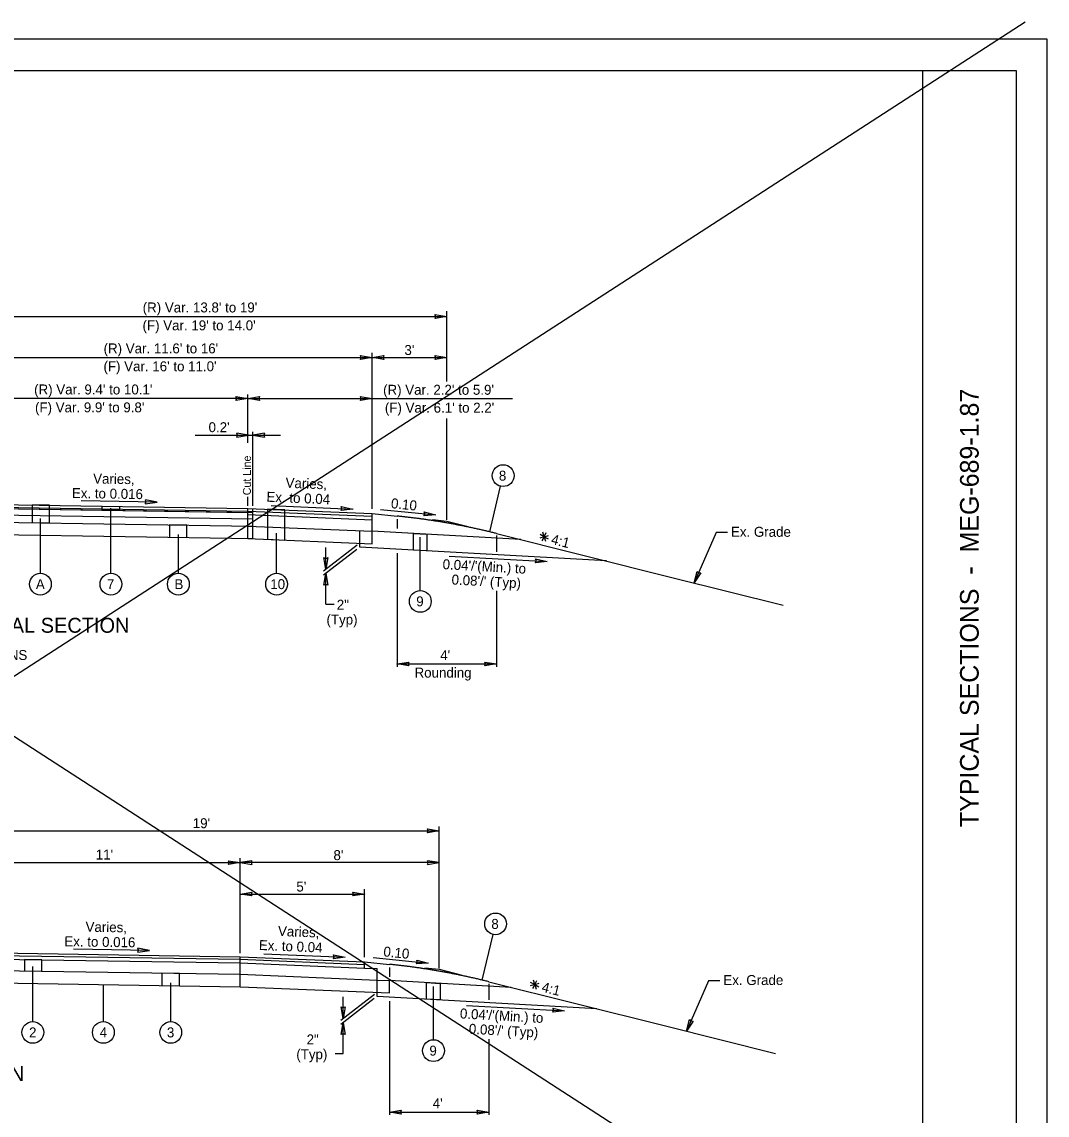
# Model space of a CAD drawing. Extents: x -268 to 840, y -210 to 226.
# Drawn here: x 400.5 to 482.9, y 24.1 to 112 of the extents above; entities that cross this region are included whole.
import ezdxf

# ---------------------------------------------------------------- set-up
doc = ezdxf.new("R2010")
doc.units = 0
for name, color, linetype in [('Level 1', 7, 'Continuous'), ('Level 16', 7, 'Continuous'), ('PV_X_Shoulder', 7, 'Continuous'), ('SH_Border', 7, 'Continuous'), ('SH_Data', 7, 'Continuous'), ('XS_P_Finished_Grade', 7, 'Continuous'), ('XS_X_Pavt', 7, 'Continuous')]:
    doc.layers.add(name, color=color, linetype=linetype)

msp = doc.modelspace()

# ---------------------------------------------------------------- linework, layer by layer
at = {"layer": 'Level 1'}
msp.add_lwpolyline([(312.91, 0.555), (482.91, 0.555), (482.91, 110.555), (312.91, 110.555)], close=True, dxfattribs=at)
at = {"layer": 'Level 16'}
msp.add_line((472.91, 3.055), (472.91, 108.055), dxfattribs=at)
msp.add_lwpolyline([(320.41, 108.055), (480.41, 108.055), (480.41, 3.055), (320.41, 3.055)], close=True, dxfattribs=at)
at = {"layer": 'PV_X_Shoulder'}
for p, q in [((311.141, 111.953), (481.141, 1.953)), ((311.141, 1.953), (481.141, 111.953))]:
    msp.add_line(p, q, dxfattribs=at)
at = {"layer": 'SH_Border'}
for points in [[(434.653, 88.284), (434.657, 88.282)], [(434.655, 88.284), (434.658, 88.282)], [(428.653, 84.984), (428.657, 84.982)], [(428.655, 84.984), (428.658, 84.982)], [(428.665, 84.981), (428.663, 84.983)], [(428.667, 84.981), (428.663, 84.983)], [(434.653, 84.984), (434.657, 84.982)], [(434.655, 84.984), (434.658, 84.982)], [(418.653, 81.684), (418.657, 81.682)], [(418.655, 81.684), (418.658, 81.682)], [(418.665, 81.681), (418.663, 81.683)], [(418.667, 81.681), (418.663, 81.683)], [(428.653, 81.684), (428.657, 81.682)], [(428.655, 81.684), (428.658, 81.682)], [(418.72, 78.726), (418.724, 78.728)], [(418.722, 78.726), (418.725, 78.728)], [(419.065, 78.729), (419.063, 78.727)], [(419.067, 78.729), (419.063, 78.727)], [(411.374, 73.348), (411.378, 73.35)], [(411.376, 73.348), (411.378, 73.35)], [(427.104, 72.804), (427.108, 72.802)], [(427.106, 72.805), (427.108, 72.802)], [(433.775, 72.33), (433.778, 72.328)], [(433.776, 72.331), (433.779, 72.328)], [(442.732, 68.576), (442.736, 68.574)], [(442.734, 68.577), (442.736, 68.574)], [(424.946, 67.956), (424.944, 67.952)], [(424.946, 67.954), (424.944, 67.952)], [(424.942, 67.623), (424.945, 67.625)], [(424.943, 67.621), (424.945, 67.625)], [(454.54, 66.868), (454.536, 66.866)], [(454.54, 66.87), (454.537, 66.867)], [(430.665, 60.346), (430.663, 60.349)], [(430.667, 60.347), (430.663, 60.349)], [(438.653, 60.349), (438.657, 60.347)], [(438.655, 60.35), (438.658, 60.347)], [(434.044, 46.938), (434.048, 46.936)], [(434.046, 46.938), (434.049, 46.936)], [(418.044, 44.383), (418.048, 44.381)], [(418.046, 44.383), (418.049, 44.381)], [(418.056, 44.383), (418.054, 44.381)], [(418.058, 44.383), (418.054, 44.381)], [(434.044, 44.38), (434.048, 44.382)], [(434.046, 44.38), (434.049, 44.382)], [(418.056, 41.858), (418.054, 41.861)], [(418.058, 41.859), (418.054, 41.861)], [(428.044, 41.861), (428.048, 41.859)], [(428.046, 41.862), (428.048, 41.859)], [(410.765, 37.324), (410.768, 37.326)], [(410.767, 37.324), (410.769, 37.326)], [(426.495, 36.78), (426.499, 36.778)], [(426.497, 36.781), (426.499, 36.778)], [(433.165, 36.306), (433.169, 36.304)], [(433.167, 36.306), (433.17, 36.304)], [(426.336, 31.849), (426.335, 31.845)], [(426.337, 31.847), (426.335, 31.844)], [(444.123, 32.469), (444.126, 32.467)], [(444.125, 32.469), (444.127, 32.467)], [(426.333, 31.516), (426.336, 31.518)], [(426.334, 31.514), (426.336, 31.517)], [(453.931, 30.846), (453.927, 30.843)], [(453.931, 30.844), (453.927, 30.842)], [(430.056, 24.322), (430.054, 24.325)], [(430.058, 24.323), (430.054, 24.325)], [(438.044, 24.325), (438.048, 24.323)], [(438.046, 24.326), (438.048, 24.323)]]:
    msp.add_lwpolyline(points, dxfattribs=at)
at = {"layer": 'SH_Data'}
for p, q in [((396.66, 88.283), (434.66, 88.283)), ((433.711, 88.441), (434.66, 88.283)), ((434.66, 88.283), (433.714, 88.124)), ((433.714, 88.124), (433.714, 88.124)), ((434.66, 83.061), (434.66, 88.711)), ((428.66, 72.816), (428.66, 85.363)), ((396.66, 84.983), (428.66, 84.983)), ((427.711, 85.141), (428.66, 84.983)), ((428.66, 84.983), (427.714, 84.824)), ((427.714, 84.824), (427.714, 84.824)), ((428.66, 84.983), (429.607, 85.141)), ((429.61, 84.824), (428.66, 84.983)), ((428.66, 84.983), (434.66, 84.983)), ((429.607, 85.141), (429.607, 85.141)), ((433.71, 85.141), (434.66, 84.983)), ((434.66, 84.983), (433.714, 84.824)), ((433.714, 84.824), (433.714, 84.824)), ((417.711, 81.841), (418.66, 81.683)), ((418.66, 78.118), (418.66, 82.001)), ((418.66, 81.683), (419.607, 81.841)), ((419.607, 81.841), (419.607, 81.841)), ((427.71, 81.841), (428.66, 81.683)), ((418.66, 81.683), (396.66, 81.683)), ((418.66, 81.683), (417.714, 81.524)), ((417.714, 81.524), (417.714, 81.524)), ((419.61, 81.524), (418.66, 81.683)), ((418.66, 81.683), (428.66, 81.683)), ((428.66, 81.683), (427.714, 81.524)), ((427.714, 81.524), (427.714, 81.524)), ((428.66, 81.683), (439.952, 81.683)), ((434.66, 71.93), (434.66, 80.067)), ((414.437, 78.728), (418.727, 78.728)), ((417.778, 78.569), (418.727, 78.728)), ((418.727, 78.728), (417.781, 78.886)), ((417.781, 78.886), (417.781, 78.886)), ((418.727, 78.728), (419.06, 78.728)), ((419.06, 73.047), (419.06, 79.014)), ((420.01, 78.886), (419.06, 78.728)), ((419.06, 78.728), (420.007, 78.569)), ((419.06, 78.728), (421.306, 78.728)), ((420.007, 78.569), (420.007, 78.569)), ((438.107, 70.968), (438.984, 74.632)), ((396.66, 73.198), (418.66, 72.849)), ((396.66, 72.989), (418.66, 72.641)), ((411.381, 73.349), (405.268, 73.447)), ((410.428, 73.214), (411.381, 73.349)), ((411.381, 73.349), (410.438, 73.53)), ((410.438, 73.53), (410.438, 73.53)), ((418.66, 73.058), (418.66, 73.78)), ((420.553, 73.076), (427.111, 72.803)), ((426.169, 73), (427.111, 72.803)), ((396.66, 72.864), (418.658, 72.516)), ((401.995, 67.638), (401.995, 72.051)), ((407.668, 67.638), (407.668, 72.873)), ((418.66, 72.849), (428.66, 72.433)), ((418.66, 72.516), (418.66, 72.849)), ((418.66, 72.641), (428.66, 72.224)), ((418.66, 70.433), (418.66, 72.516)), ((418.664, 72.349), (428.66, 71.933)), ((421.639, 70.308), (421.639, 72.725)), ((427.111, 72.803), (426.159, 72.684)), ((426.159, 72.684), (426.159, 72.684)), ((428.66, 71.933), (428.66, 72.433)), ((428.66, 72.433), (430.66, 72.233)), ((429.34, 72.772), (433.782, 72.328)), ((433.782, 72.328), (432.824, 72.265)), ((432.824, 72.265), (432.824, 72.265)), ((432.852, 72.58), (433.782, 72.328)), ((413.777, 70.509), (413.777, 71.51)), ((418.67, 71.432), (428.66, 71.016)), ((428.66, 71.016), (428.66, 71.933)), ((430.66, 71.976), (430.66, 71.226)), ((433.51, 71.948), (434.66, 71.833)), ((434.66, 71.833), (436.389, 71.4)), ((412.377, 70.532), (413.777, 70.509)), ((413.085, 67.638), (413.085, 70.747)), ((418.675, 70.432), (428.66, 70.016)), ((420.239, 70.367), (421.639, 70.308)), ((420.98, 67.638), (420.98, 70.851)), ((427.66, 70.058), (427.66, 71.058)), ((428.66, 70.016), (428.66, 71.016)), ((440.602, 70.347), (428.66, 71.016)), ((432.533, 66.255), (432.533, 70.532)), ((438.66, 70.833), (452.853, 67.284)), ((438.66, 70.664), (438.66, 69.37)), ((442.484, 70.572), (442.125, 70.463)), ((442.484, 70.572), (442.153, 70.749)), ((442.484, 70.572), (442.307, 70.241)), ((442.484, 70.572), (442.374, 70.931)), ((442.484, 70.572), (442.66, 70.903)), ((442.484, 70.572), (442.842, 70.682)), ((442.484, 70.572), (442.815, 70.396)), ((442.484, 70.572), (442.593, 70.214)), ((456.316, 70.906), (454.536, 66.864)), ((457.217, 70.906), (456.316, 70.906)), ((427.435, 69.561), (424.744, 67.473)), ((427.448, 69.893), (424.747, 67.796)), ((424.944, 67.949), (424.944, 69.697)), ((427.66, 69.737), (427.66, 70.07)), ((447.486, 68.626), (427.66, 69.737)), ((424.944, 67.949), (424.786, 68.896)), ((424.786, 68.896), (424.786, 68.896)), ((425.102, 68.899), (424.944, 67.949)), ((430.66, 69.262), (430.66, 60.13)), ((434.862, 69.016), (442.739, 68.575)), ((442.739, 68.575), (441.784, 68.481)), ((441.802, 68.797), (442.739, 68.575)), ((441.784, 68.481), (441.784, 68.481)), ((454.536, 66.864), (454.776, 67.793)), ((455.066, 67.668), (454.536, 66.864)), ((454.776, 67.793), (454.776, 67.793)), ((424.786, 66.678), (424.944, 67.628)), ((424.944, 65.155), (424.944, 67.628)), ((424.944, 67.628), (425.102, 66.681)), ((452.853, 67.284), (461.689, 65.076)), ((425.102, 66.681), (425.102, 66.681)), ((438.66, 66.226), (438.66, 60.13)), ((424.944, 65.155), (425.603, 65.155)), ((430.66, 60.348), (431.607, 60.506)), ((431.61, 60.19), (430.66, 60.348)), ((430.66, 60.348), (438.66, 60.348)), ((431.607, 60.506), (431.607, 60.506)), ((437.71, 60.506), (438.66, 60.348)), ((438.66, 60.348), (437.714, 60.19)), ((437.714, 60.19), (437.714, 60.19)), ((396.051, 46.936), (434.051, 46.936)), ((433.101, 47.094), (434.051, 46.936)), ((434.051, 46.936), (433.105, 46.778)), ((433.105, 46.778), (433.105, 46.778)), ((434.051, 35.906), (434.051, 47.277)), ((396.051, 44.382), (418.051, 44.382)), ((417.101, 44.54), (418.051, 44.382)), ((418.051, 44.382), (417.105, 44.223)), ((417.105, 44.223), (417.105, 44.223)), ((418.051, 37.106), (418.051, 44.749)), ((419.001, 44.54), (418.051, 44.382)), ((434.051, 44.382), (418.051, 44.382)), ((418.051, 44.382), (418.998, 44.223)), ((418.998, 44.223), (418.998, 44.223)), ((433.102, 44.223), (434.051, 44.382)), ((434.051, 44.382), (433.105, 44.54)), ((433.105, 44.54), (433.105, 44.54)), ((428.051, 36.792), (428.051, 42.253)), ((418.051, 41.86), (418.998, 42.018)), ((419.001, 41.702), (418.051, 41.86)), ((418.051, 41.86), (428.051, 41.86)), ((418.998, 42.018), (418.998, 42.018)), ((427.101, 42.018), (428.051, 41.86)), ((428.051, 41.86), (427.104, 41.702)), ((427.104, 41.702), (427.104, 41.702)), ((437.497, 34.944), (438.375, 38.608)), ((396.051, 37.173), (418.051, 36.825)), ((396.051, 36.965), (418.051, 36.617)), ((410.771, 37.325), (404.659, 37.423)), ((409.818, 37.19), (410.771, 37.325)), ((410.771, 37.325), (409.829, 37.506)), ((409.829, 37.506), (409.829, 37.506)), ((419.944, 37.052), (426.502, 36.778)), ((425.559, 36.976), (426.502, 36.778)), ((396.051, 36.673), (418.055, 36.325)), ((401.386, 31.613), (401.386, 36.027)), ((418.051, 36.825), (428.051, 36.409)), ((418.051, 34.408), (418.051, 36.825)), ((418.051, 34.377), (418.051, 36.793)), ((418.051, 36.617), (428.051, 36.2)), ((418.055, 36.325), (428.051, 35.909)), ((426.502, 36.778), (425.549, 36.66)), ((425.549, 36.66), (425.549, 36.66)), ((428.051, 35.909), (428.051, 36.409)), ((428.051, 36.409), (430.051, 36.209)), ((428.731, 36.748), (433.172, 36.304)), ((433.172, 36.304), (432.215, 36.241)), ((432.215, 36.241), (432.215, 36.241)), ((432.243, 36.556), (433.172, 36.304)), ((396.051, 35.757), (418.061, 35.408)), ((413.168, 34.485), (413.168, 35.486)), ((418.061, 35.408), (429.051, 34.95)), ((428.051, 35.909), (429.051, 35.867)), ((429.051, 34.95), (429.051, 35.867)), ((430.051, 35.952), (430.051, 35.202)), ((432.901, 35.924), (434.051, 35.809)), ((434.051, 35.809), (435.78, 35.376)), ((396.051, 34.756), (418.066, 34.408)), ((407.058, 31.613), (407.058, 34.582)), ((411.768, 34.508), (413.168, 34.485)), ((412.476, 31.613), (412.476, 34.723)), ((418.066, 34.408), (430.051, 33.909)), ((429.051, 34.95), (430.051, 34.909)), ((429.051, 33.95), (429.051, 34.95)), ((430.051, 33.909), (430.051, 34.909)), ((439.845, 34.36), (430.051, 34.909)), ((433.59, 30.148), (433.59, 34.424)), ((438.051, 34.809), (452.244, 31.26)), ((438.051, 34.639), (438.051, 33.346)), ((441.727, 34.585), (441.368, 34.476)), ((441.727, 34.585), (441.396, 34.762)), ((441.727, 34.585), (441.55, 34.254)), ((441.727, 34.585), (441.617, 34.944)), ((441.727, 34.585), (441.903, 34.916)), ((441.727, 34.585), (442.085, 34.694)), ((441.727, 34.585), (442.058, 34.409)), ((441.727, 34.585), (441.836, 34.227)), ((455.707, 34.882), (453.927, 30.84)), ((456.608, 34.882), (455.707, 34.882)), ((428.826, 33.454), (426.135, 31.365)), ((428.839, 33.785), (426.138, 31.689)), ((426.335, 31.842), (426.335, 33.59)), ((429.051, 33.629), (429.051, 33.963)), ((446.729, 32.639), (429.051, 33.629)), ((426.335, 31.842), (426.177, 32.788)), ((426.177, 32.788), (426.177, 32.788)), ((426.493, 32.791), (426.335, 31.842)), ((430.051, 33.238), (430.051, 24.106)), ((436.253, 32.908), (444.13, 32.467)), ((443.193, 32.69), (444.13, 32.467)), ((444.13, 32.467), (443.174, 32.374)), ((443.174, 32.374), (443.174, 32.374)), ((453.927, 30.84), (454.167, 31.769)), ((454.457, 31.643), (453.927, 30.84)), ((454.167, 31.769), (454.167, 31.769)), ((426.177, 30.571), (426.335, 31.521)), ((426.335, 29.048), (426.335, 31.521)), ((426.335, 31.521), (426.493, 30.574)), ((452.244, 31.26), (461.08, 29.052)), ((426.493, 30.574), (426.493, 30.574)), ((438.051, 30.202), (438.051, 24.106)), ((425.676, 29.048), (426.335, 29.048)), ((430.051, 24.324), (430.998, 24.482)), ((431.001, 24.166), (430.051, 24.324)), ((430.051, 24.324), (438.051, 24.324)), ((430.998, 24.482), (430.998, 24.482)), ((437.101, 24.482), (438.051, 24.324)), ((438.051, 24.324), (437.104, 24.166)), ((437.104, 24.166), (437.104, 24.166))]:
    msp.add_line(p, q, dxfattribs=at)
for points in [[(402.724, 71.685), (402.724, 73.102), (401.324, 73.124), (401.324, 71.707)], [(406.962, 73.034), (408.362, 73.012), (408.362, 72.679), (406.962, 72.701)], [(431.975, 70.83), (433.065, 70.769), (433.065, 69.434), (431.975, 69.495)], [(402.115, 35.661), (402.115, 36.577), (400.715, 36.599), (400.715, 35.683)], [(433.025, 34.742), (434.115, 34.681), (434.115, 33.346), (433.025, 33.407)]]:
    msp.add_lwpolyline(points, close=True, dxfattribs=at)
for points in [[(421.639, 72.725), (420.239, 72.783), (420.239, 70.367)], [(413.777, 71.51), (412.377, 71.532), (412.377, 70.532)], [(413.168, 35.486), (411.768, 35.508), (411.768, 34.508)]]:
    msp.add_lwpolyline(points, dxfattribs=at)
for centre in [(439.188, 75.483), (401.995, 66.763), (407.668, 66.763), (413.085, 66.763), (420.98, 66.763), (432.533, 65.38), (438.579, 39.459), (401.386, 30.738), (407.058, 30.738), (412.476, 30.738), (433.59, 29.273)]:
    msp.add_circle(centre, 0.875, dxfattribs=at)
for centre, start, end in [((433.472, 88.28), 327.14123, 33.822), ((427.472, 84.98), 327.14123, 33.822), ((429.849, 84.984), 147.14123, 213.822), ((433.472, 84.981), 327.14123, 33.822), ((417.472, 81.68), 327.14123, 33.822), ((419.849, 81.684), 147.14123, 213.822), ((427.472, 81.681), 327.14123, 33.822), ((417.539, 78.73), 326.178, 32.85877), ((420.249, 78.726), 146.178, 212.85877), ((410.192, 73.38), 324.80397, 31.48474), ((425.923, 72.85), 324.75531, 31.43608), ((432.598, 72.444), 321.43103, 28.1118), ((424.942, 69.138), 237.14123, 303.822), ((441.553, 68.654), 323.22836, 29.90912), ((455.017, 67.951), 213.17538, 279.85615), ((424.946, 66.439), 57.14123, 123.822), ((431.849, 60.35), 147.14123, 213.822), ((437.472, 60.346), 327.14123, 33.822), ((432.862, 46.934), 327.14123, 33.822), ((416.862, 44.379), 327.14123, 33.822), ((419.24, 44.38), 146.178, 212.85877), ((432.863, 44.383), 326.178, 32.85877), ((419.24, 41.862), 147.14123, 213.822), ((426.862, 41.858), 327.14123, 33.822), ((409.583, 37.356), 324.80397, 31.48474), ((425.314, 36.826), 324.75531, 31.43608), ((431.989, 36.42), 321.43103, 28.1118), ((426.333, 33.03), 237.14123, 303.822), ((442.943, 32.546), 323.22836, 29.90912), ((454.408, 31.927), 213.17538, 279.85615), ((426.337, 30.332), 57.14123, 123.822), ((431.24, 24.326), 147.14123, 213.822), ((436.863, 24.322), 327.14123, 33.822)]:
    msp.add_arc(centre, 0.288, start, end, dxfattribs=at)
for points in [[(438.66, 70.833), (438.506, 70.871), (438.353, 70.909), (438.199, 70.946), (438.045, 70.983), (437.891, 71.019), (437.737, 71.055), (437.583, 71.091), (437.43, 71.126), (437.276, 71.161), (437.122, 71.195), (436.968, 71.229), (436.814, 71.262), (436.66, 71.295), (436.506, 71.328), (436.353, 71.36), (436.199, 71.391), (436.045, 71.422), (435.891, 71.453), (435.737, 71.483), (435.583, 71.513), (435.43, 71.543), (435.276, 71.571), (435.122, 71.6), (434.968, 71.628), (434.814, 71.656), (434.66, 71.683), (434.506, 71.709), (434.353, 71.736), (434.199, 71.761), (434.045, 71.787), (433.891, 71.812), (433.737, 71.836), (433.583, 71.86), (433.43, 71.884), (433.276, 71.907), (433.122, 71.93), (432.968, 71.952), (432.814, 71.974), (432.66, 71.995), (432.506, 72.016), (432.353, 72.037), (432.199, 72.057), (432.045, 72.076), (431.891, 72.095), (431.737, 72.114), (431.583, 72.132), (431.43, 72.15), (431.276, 72.168), (431.122, 72.185), (430.968, 72.201), (430.814, 72.217), (430.66, 72.233)], [(438.051, 34.809), (437.897, 34.847), (437.743, 34.885), (437.59, 34.922), (437.436, 34.959), (437.282, 34.995), (437.128, 35.031), (436.974, 35.067), (436.82, 35.102), (436.667, 35.137), (436.513, 35.171), (436.359, 35.205), (436.205, 35.238), (436.051, 35.271), (435.897, 35.304), (435.743, 35.336), (435.59, 35.367), (435.436, 35.398), (435.282, 35.429), (435.128, 35.459), (434.974, 35.489), (434.82, 35.518), (434.667, 35.547), (434.513, 35.576), (434.359, 35.604), (434.205, 35.631), (434.051, 35.659), (433.897, 35.685), (433.743, 35.712), (433.59, 35.737), (433.436, 35.763), (433.282, 35.788), (433.128, 35.812), (432.974, 35.836), (432.82, 35.86), (432.667, 35.883), (432.513, 35.906), (432.359, 35.928), (432.205, 35.95), (432.051, 35.971), (431.897, 35.992), (431.743, 36.013), (431.59, 36.033), (431.436, 36.052), (431.282, 36.071), (431.128, 36.09), (430.974, 36.108), (430.82, 36.126), (430.667, 36.144), (430.513, 36.16), (430.359, 36.177), (430.205, 36.193), (430.051, 36.209)]]:
    msp.add_spline(points, degree=3, dxfattribs=at)
at = {"layer": 'XS_P_Finished_Grade'}
for p, q in [((396.66, 72.364), (419.06, 72.009)), ((396.693, 72.864), (419.06, 72.509)), ((419.06, 70.433), (419.06, 72.833)), ((396.66, 71.781), (419.06, 71.427)), ((396.66, 70.787), (419.06, 70.433))]:
    msp.add_line(p, q, dxfattribs=at)

# ---------------------------------------------------------------- texts
at = {"layer": 'SH_Data'}
for s, height, p in [("(R) Var. 13.8' to 19'", 0.8, (410.219, 88.601)), ("(F) Var. 19' to 14.0'", 0.8, (410.208, 87.161)), ("(R) Var. 11.6' to 16'", 0.8, (407.077, 85.31)), ("3'", 0.8, (431.255, 85.183)), ("(F) Var. 16' to 11.0'", 0.8, (407.069, 83.87)), ("(R) Var. 9.4' to 10.1'", 0.8, (401.494, 82.01)), ("(R) Var. 2.2' to 5.9'", 0.8, (429.54, 81.984)), ("(F) Var. 9.9' to 9.8'", 0.8, (401.565, 80.57)), ("(F) Var. 6.1' to 2.2'", 0.8, (429.683, 80.544)), ("0.2'", 0.8, (415.514, 78.976)), ('8', 0.8, (438.848, 75.083)), ('Ex. Grade', 0.8, (457.499, 70.57)), ('A', 0.8, (401.634, 66.363)), ('7', 0.8, (407.343, 66.363)), ('B', 0.8, (412.773, 66.363)), ('10', 0.8, (420.474, 66.363)), ('2"', 0.8, (425.82, 64.712)), ('9', 0.8, (432.206, 64.98)), ('(Typ)', 0.8, (424.991, 63.522)), ('PAVEMENT WIDENING - NORMAL SECTION', 1.2, (375.811, 62.857)), ('LIMITING STATIONS', 0.8, (390.663, 60.671)), ("4'", 0.8, (434.136, 60.656)), ('Rounding', 0.8, (432.07, 59.256)), ("19'", 0.8, (414.244, 47.153)), ("11'", 0.8, (406.448, 44.633)), ("8'", 0.8, (425.552, 44.587)), ("5'", 0.8, (422.569, 42.06)), ('8', 0.8, (438.239, 39.059)), ('Ex. Grade', 0.8, (456.89, 34.546)), ('2', 0.8, (401.087, 30.338)), ('4', 0.8, (406.762, 30.338)), ('3', 0.8, (412.167, 30.338)), ('2"', 0.8, (423.394, 29.774)), ('(Typ)', 0.8, (422.566, 28.583)), ('9', 0.8, (433.263, 28.873)), ('TYPICAL SECTION', 1.2, (386.428, 26.832)), ("4'", 0.8, (433.527, 24.632))]:
    msp.add_text(s, height=height, dxfattribs=at).set_placement(p)
for s, height, rotation, p in [('Cut Line', 0.64, 90, (418.916, 73.909)), ('Varies,', 0.8, 359.08305, (406.232, 74.852)), ('Varies,', 0.8, 357.61408, (421.689, 74.519)), ('Ex. to 0.016', 0.8, 359.08305, (404.525, 73.688)), ('Ex. to 0.04', 0.8, 357.61408, (420.154, 73.392)), ('0.10', 0.8, 354.2898, (430.145, 72.879)), ('4:1', 0.8, 345.96376, (442.984, 70.013)), ("0.04'/'(Min.) to", 0.8, 356.79433, (434.307, 67.978)), ("0.08'/' (Typ)", 0.8, 356.79433, (435.026, 66.746)), ('Varies,', 0.8, 359.08305, (405.623, 38.828)), ('Varies,', 0.8, 357.61408, (421.08, 38.495)), ('Ex. to 0.016', 0.8, 359.08305, (403.916, 37.664)), ('Ex. to 0.04', 0.8, 357.61408, (419.545, 37.367)), ('0.10', 0.8, 354.2898, (429.536, 36.854)), ('4:1', 0.8, 345.96376, (442.227, 34.026)), ("0.04'/'(Min.) to", 0.8, 356.79433, (435.698, 31.871)), ("0.08'/' (Typ)", 0.8, 356.79433, (436.417, 30.638))]:
    msp.add_text(s, height=height, rotation=rotation, dxfattribs=at).set_placement(p)
at = {"layer": 'XS_X_Pavt'}
msp.add_text('TYPICAL SECTIONS  -  MEG-689-1.87', height=1.5, rotation=90, dxfattribs=at).set_placement((477.41, 47.241))

doc.saveas('drawing.dxf')
